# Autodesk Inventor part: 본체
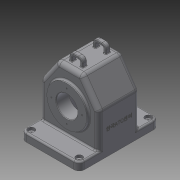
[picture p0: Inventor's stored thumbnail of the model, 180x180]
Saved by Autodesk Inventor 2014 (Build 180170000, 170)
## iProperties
Created: 2016-12
Part Number: 본체
Material: 일반
Document SubType Name: Modeling
Designer: USER
Density: 1 g/cm^3
Appearance: 기본값
Author: USER
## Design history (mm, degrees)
sketch "스케치1"
  geometry: L1 (0, 0)-(110, 0); L2 (110, 0)-(110, 80); L3 (110, 80)-(78.491, 125); L4 (78.491, 125)-(31.509, 125); L5 (31.509, 125)-(0, 80); L6 (0, 80)-(0, 0)
  constraints: 12 end point, 2 parallel, 1 horizontal, 1 perpendicular
  dimensions: "d0" = 80 distance of L1.end L2.end; "d1" = 35 deg angle of L6 L5; "d2" = 35 deg angle of L2 L3; "d3" = 125 vertical distance of L1.start L4.end; "d4" = 110 distance of L1.start L1.end; "d5" = 80 distance of L1.start L5.end
extrude "돌출1" new body sketch "스케치1" distance "d6" = 77; taper "d7" = 0 deg
node "작업 평면1"
sketch "스케치2"
  geometry: L1 (31.509, 125)-(0, 80) reference; L2 (78.491, 125)-(31.509, 125) reference; L3 (110, 80)-(78.491, 125) reference; L4 (0, 0)-(110, 0) reference; L5 (0, 80)-(0, 0) reference; L6 (31.509, 125)-(0, 80) reference; L7 (78.491, 125)-(31.509, 125) reference; L8 (110, 80)-(78.491, 125) reference; L9 (110, 0)-(110, 80) reference; L10 (105, 78.424)-(75.888, 120); L11 (75.888, 120)-(34.112, 120); L12 (34.112, 120)-(5, 78.424); L13 (5, 78.424)-(5, 0); L14 (105, 0)-(105, 78.424); L15 (5, 0)-(105, 0); 1 further point
  constraints: 12 end point, 2 point on line, 1 perpendicular, 2 other
  dimensions: "d8" = 5 distance between parallel lines of L2 L11; "d9" = 5 distance between parallel lines of L9 L14; "d10" = 5 distance between parallel lines of L5 L13
extrude "돌출2" cut sketch "스케치2" stored distance "d11" = 67; taper "d12" = 0 deg
node "작업 평면2"
sketch "스케치3"
  geometry: L1 (78.491, 125)-(31.509, 125) reference; C1 r 37.5 at (55, 65); 2 further points
  constraints: 1 centre point, 1 midpoint, 1 vertical alignment
  dimensions: "d13" = 75 diameter of C1; "d14" = 65 vertical distance of point (0, 0) C1.centre
extrude "돌출3" join sketch "스케치3" distance "d15" = 5; taper "d16" = 0 deg
sketch "스케치4"
  geometry: L1 (-78.491, 125)-(-31.509, 125) reference; C1 r 31 at (-55, 65); 2 further points
  constraints: 1 centre point, 1 midpoint, 1 vertical alignment
  dimensions: "d17" = 62 diameter of C1; "d18" = 65 vertical distance of point (-110, 0) C1.centre
extrude "돌출4" join sketch "스케치4" distance "d19" = 10; taper "d20" = 0 deg
sketch "스케치5"
  geometry: C1 r 31 at (0, 0) reference; C2 r 20 at (0, 0); 1 further point
  constraints: 1 centre point, 1 coincident
  dimensions: "d21" = 40 diameter of C2
extrude "돌출5" cut sketch "스케치5" distance "d22" = 15; taper "d23" = 0 deg
node "작업 평면4"
sketch "스케치7"
  geometry: L1 (102.5, 82)-(27.5, 82) reference; L2 (65, 72)-(65, 58); L3 (120, 72)-(78.424, 72) reference; L4 (120, 5)-(120, 72) reference; L5 (78.424, 72)-(0, 72) reference; L6 (65, 58)-(92, 58); L7 (92, 58)-(106, 72); L8 (106, 72)-(65, 72); 2 further points
  constraints: 8 end point, 2 point on line, 1 midpoint, 1 parallel, 1 perpendicular, 1 vertical alignment
  dimensions: "d28" = 27 distance of L2.end L6.end; "d29" = 45 deg angle of L6 L7; "d30" = 24 vertical distance of L1.end L2.end
revolve "회전1" sketch "스케치7" stored, may be unused: angle "d31" = 90 deg
sketch "스케치6"
  geometry: C1 r 37.5 at (0, 0) reference; C2 r 20 at (0, 0); 1 further point
  constraints: 1 centre point, 1 coincident
  dimensions: "d24" = 40 diameter of C2
extrude "돌출6" cut sketch "스케치6" distance "d25" = 24; taper "d26" = 0 deg
node "작업 평면3"
sketch "스케치9"
  geometry: L1 (-110, 113.5)-(0, 113.5); L2 (0, 113.5)-(0, -36.5); L3 (0, -36.5)-(-110, -36.5); L4 (-110, -36.5)-(-110, 113.5); L5 (-110, 0)-(-110, 77) reference; 3 further points
  constraints: 8 end point, 2 midpoint, 2 parallel, 1 coincident, 1 horizontal, 1 perpendicular, 1 vertical alignment
  dimensions: "d35" = 150 distance of L3.end L1.start; "d36" = 110 distance of L2.end L3.end
extrude "돌출8" join sketch "스케치9" distance "d37" = 15; taper "d38" = 0 deg
sketch "스케치10"
  geometry: L1 (92.5, -31.5)-(17.5, -31.5) reference; L2 (5, -108.5)-(105, -108.5) reference; L3 (5, -108.5)-(105, -108.5) reference; L4 (5, -41.5)-(5, -108.5) reference; L5 (105, -41.5)-(5, -41.5) reference; L6 (105, -108.5)-(105, -41.5) reference; 1 further point
extrude "돌출9" cut sketch "스케치10" distance "d39" = 15; taper "d40" = 0 deg
node "작업 평면5"
node "작업 평면6"
sketch "스케치11"
  geometry: L1 (-78.491, 125)-(-31.509, 125) reference; L2 (-67.5, 125)-(-67.5, 140); L3 (-67.5, 140)-(-42.5, 140); L4 (-42.5, 140)-(-42.5, 125); L5 (-62.5, 125)-(-62.5, 135); L6 (-62.5, 135)-(-47.5, 135); L7 (-47.5, 135)-(-47.5, 125); L8 (-5, 0)-(-105, 0) reference; 4 further points
  constraints: 12 end point, 5 perpendicular, 4 point on line, 3 midpoint, 2 vertical alignment, 1 parallel
  dimensions: "d42" = 25 distance of L2.end L3.end; "d43" = 15 distance of L5.end L6.end; "d44" = 140 vertical distance of L2.end L8.end; "d45" = 135 distance from line of L8.end L6
extrude "돌출10" join sketch "스케치11" distance "d46" = 8; taper "d47" = 0 deg
node "작업 평면7"
sketch "스케치12"
  geometry: L1 (-67.5, 125)-(-62.5, 125) reference; L2 (-67.5, 125)-(-67.5, 140) reference; L3 (-67.5, 140)-(-42.5, 140) reference; L4 (-42.5, 140)-(-42.5, 125) reference; L5 (-47.5, 125)-(-42.5, 125) reference; L6 (-47.5, 125)-(-47.5, 135) reference; L7 (-47.5, 135)-(-62.5, 135) reference; L8 (-62.5, 135)-(-62.5, 125) reference; 1 further point
extrude "돌출11" join sketch "스케치12" distance "d49" = 8; taper "d50" = 0 deg
fillet "모깎기1" dims "d51" = 8
fillet "모깎기2" dims "d52" = 8, "d100" = 10
fillet "모깎기3" dims "d53" = 8
fillet "모깎기4" dims "d54" = 3
fillet "모깎기5" dims "d55" = 3
fillet "모깎기6" dims "d56" = 8
fillet "모깎기7" dims "d57" = 1
fillet "모깎기8" dims "d58" = 1
fillet "모깎기9" dims "d59" = 3
fillet "모깎기10" dims "d60" = 1
fillet "모깎기11" dims "d61" = 3
fillet "모깎기12" dims "d62" = 1
fillet "모깎기13" dims "d63" = 3
fillet "모깎기14" dims "d64" = 10
chamfer "모따기1" distance "d65" = 1; stored, may be unused: second distance "d66" = 2, angle "d67" = 45 deg
fillet "모깎기15" dims "d68" = 3
sketch "스케치13"
  geometry: L1 (10, 33.5)-(100, 33.5) reference; L2 (3, 1.798)-(3, 26.5) reference; L3 (102, 3)-(8, 3) reference; L4 (107, 26.5)-(107, 1.798) reference; A1 r 7 centre (10, -103.5) between (3, -103.5) and (10, -110.5) reference; A2 r 7 centre (100, -103.5) between (100, -110.5) and (107, -103.5) reference; A3 r 7 centre (100, 26.5) between (107, 26.5) and (100, 33.5) reference; A4 r 7 centre (10, 26.5) between (10, 33.5) and (3, 26.5) reference; A5 r 11 centre (8, -8) between (8, 3) and (3, 1.798) reference; A6 r 11 centre (102, -8) between (107, 1.798) and (102, 3) reference; 5 further points
  constraints: 4 coincident
hole "구멍1" sketch "스케치13" at (10, -103.5), (100, -103.5), (100, 26.5), (10, 26.5) diameter "d69" = 5; stored, may be unused: countersink angle "d73" = 90 deg, drill point angle "d75" = 118 deg; dims "d70" = 6, "d71" = 12, "d72" = 5, "d74" = 8
sketch "스케치14"
  geometry: L1 (-8, 0)-(-8, -59.478) reference; 3 further points
  constraints: 1 other
  dimensions: "d76" = 45 vertical distance of point (95.5, -77.478) point (30.5, -32.478); "d77" = 38.5 horizontal distance of L1.end point (30.5, -32.478)
extrude "돌출12" join sketch "스케치14" distance "d78" = 0.5; taper "d79" = 0 deg
sketch "스케치15"
  geometry: C1 r 37.5 at (0, 0) reference; C2 r 21 at (0, 0) reference; A1 r 29 centre (0, 0) between (0, 29) and (29, 0); 3 further points
  constraints: 4 point on circle, 2 horizontal alignment, 2 vertical alignment, 1 centre point, 1 coincident
  dimensions: "d80" = 58 diameter of A1
hole "구멍2" sketch "스케치15" at (0, 29), (29, 0), (0, -29), (-29, 0) diameter "d81" = 2.459; stored, may be unused: countersink angle "d85" = 90 deg, drill point angle "d87" = 118 deg; dims "d82" = 6, "d83" = 4, "d84" = 2, "d86" = 8
sketch "스케치16"
  geometry: C1 r 20 at (0, 0) reference; C2 r 31 at (0, 0) reference; A1 r 26 centre (0, 0) between (0, 26) and (26, 0); 3 further points
  constraints: 4 point on circle, 2 horizontal alignment, 2 vertical alignment, 1 centre point, 1 coincident
  dimensions: "d88" = 52 diameter of A1
hole "구멍3" sketch "스케치16" at (0, 26), (26, 0), (0, -26), (-26, 0) diameter "d89" = 2.459; stored, may be unused: countersink angle "d93" = 90 deg, drill point angle "d95" = 118 deg; dims "d90" = 6, "d91" = 4, "d92" = 2, "d94" = 8
chamfer "모따기2" distance "d96" = 1; stored, may be unused: second distance "d97" = 2, angle "d98" = 45 deg
fillet "모깎기16" dims "d99" = 10
node "솔리드1"
node "투영된 루프1"
node "투영된 루프2"
node "투영된 루프3"
node "투영된 루프4"
other parameters: "d41" = 26, "d48" = -26
